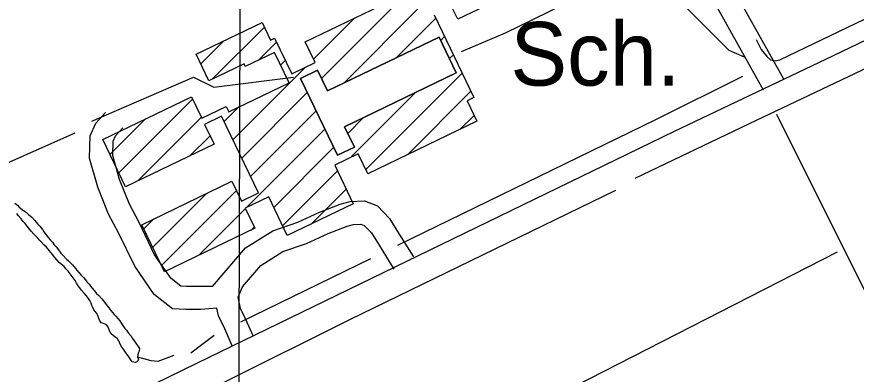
# Model space of a CAD drawing. Extents: x 3161514 to 3199414, y 831166 to 856601.
# Drawn here: x 3175919 to 3177016, y 850531 to 850998 of the extents above; entities that cross this region are included whole.
import ezdxf

# ---------------------------------------------------------------- set-up
doc = ezdxf.new("R2010")
doc.units = 0
for name, color, linetype in [('V-BLDG-IDEN', 7, 'Continuous'), ('V-BLDG-OTLN', 7, 'Continuous'), ('V-GRID-MAJR', 7, 'Continuous'), ('V-ROAD-CNTR', 7, 'Continuous'), ('V-TOPO-SHOR', 7, 'Continuous')]:
    doc.layers.add(name, color=color, linetype=linetype)

msp = doc.modelspace()

# ---------------------------------------------------------------- linework, layer by layer
at = {"layer": 'V-BLDG-OTLN'}
for p, q in [((3176317.2446730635, 850917.3385692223), (3176428.970535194, 851029.0644313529)), ((3176346.4267954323, 850911.1653525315), (3176447.5922815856, 851012.3308386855)), ((3176306.9891416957, 850942.438376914), (3176360.8049249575, 850996.2541601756)), ((3176414.524179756, 850943.9073977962), (3176466.5774924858, 850995.9607105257)), ((3176174.674165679, 850916.1894180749), (3176242.696642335, 850984.2118947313)), ((3176159.5428679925, 850936.4134594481), (3176189.186003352, 850966.0565948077)), ((3176234.9039112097, 850941.0638245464), (3176258.424099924, 850964.5840132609)), ((3176472.9441205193, 850966.9719995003), (3176478.0654100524, 850972.0932890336)), ((3176484.423525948, 850943.0960658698), (3176489.5533276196, 850948.2258675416)), ((3176201.6958582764, 850837.1450934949), (3176296.355241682, 850931.8044769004)), ((3176263.929435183, 850934.7340094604), (3176269.911375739, 850940.715950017)), ((3176375.074054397, 850798.3912552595), (3176501.0412451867, 850924.3584460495)), ((3176213.184005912, 850813.277902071), (3176298.7234474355, 850898.8173435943)), ((3176355.774596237, 850814.4471361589), (3176440.2137494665, 850898.8862893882)), ((3176430.004822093, 850817.966683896), (3176512.5291627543, 850900.4910245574)), ((3176052.5059617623, 850794.0212141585), (3176148.8372529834, 850890.3525053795)), ((3176190.207710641, 850861.0122849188), (3176209.2667676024, 850880.0713418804)), ((3176077.428119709, 850783.5880330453), (3176160.324541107, 850866.4844544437)), ((3176224.6721535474, 850789.4107106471), (3176310.2035608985, 850874.9421179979)), ((3176351.573582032, 850845.6014610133), (3176372.1154543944, 850866.1433333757)), ((3176498.1708077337, 850850.7773304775), (3176516.4984713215, 850869.1049940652)), ((3176041.017991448, 850817.8885829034), (3176087.5860779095, 850864.4566693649)), ((3176219.4736047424, 850748.8568227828), (3176321.683674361, 850851.0668924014)), ((3176145.5945323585, 850816.3991066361), (3176171.7412406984, 850842.5458149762)), ((3176254.955607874, 850748.983486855), (3176333.1637878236, 850827.1916668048)), ((3176266.443437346, 850725.1159772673), (3176338.1216935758, 850796.7942334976)), ((3176096.860817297, 850696.9547134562), (3176166.716482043, 850766.8103782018)), ((3176108.34881465, 850673.0873717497), (3176206.1678467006, 850770.9064038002)), ((3176303.924025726, 850727.2412265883), (3176349.6099119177, 850772.9271127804)), ((3176157.2476974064, 850686.6309154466), (3176217.8259444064, 850747.2091624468)), ((3176085.3728199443, 850720.822055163), (3176098.5539051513, 850734.0031403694)), ((3176225.413369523, 850719.441248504), (3176229.3135148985, 850723.3413938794))]:
    msp.add_line(p, q, dxfattribs=at)
for points in [[(3176464.512, 851000.252), (3176516.412, 850892.424), (3176507.37, 850888.072), (3176520.213, 850861.387), (3176377.757, 850792.818), (3176365.168, 850818.969), (3176334.544, 850804.2270000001), (3176358.87, 850753.689), (3176272.663, 850712.194), (3176248.3310000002, 850762.747), (3176217.492, 850747.903), (3176230.1040000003, 850721.699), (3176112.254, 850664.974), (3176082.701, 850726.373), (3176200.349, 850782.998), (3176212.784, 850757.158), (3176235.04, 850767.871), (3176186.877, 850867.932), (3176164.668, 850857.2440000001), (3176177.04, 850831.535), (3176061.271, 850775.811), (3176031.579, 850837.4990000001), (3176147.436, 850893.264), (3176160.91, 850865.268), (3176192.986, 850880.708), (3176196.298, 850873.829), (3176275.008, 850911.715), (3176255.997, 850951.216), (3176217.728, 850932.797), (3176216.1180000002, 850936.139), (3176170.292, 850914.0800000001), (3176153.535, 850948.8960000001), (3176239.7260000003, 850990.384), (3176250.807, 850967.361), (3176255.907, 850969.814), (3176278.367, 850923.147), (3176309.145, 850937.96), (3176296.08, 850965.1), (3176437.5500000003, 851033.194)], [(3176539.182, 851015.544), (3176495.394, 850994.468), (3176488.594, 851008.5970000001)]]:
    msp.add_lwpolyline(points, dxfattribs=at)
for points in [[(3176338.06, 850817.009), (3176289.856, 850917.259), (3176312.133, 850927.97), (3176325.1350000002, 850900.9280000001), (3176470.982, 850971.0530000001), (3176493.387, 850924.453), (3176347.409, 850854.264), (3176360.201, 850827.6560000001)], [(3176338.06, 850817.009), (3176360.201, 850827.6560000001), (3176347.409, 850854.264), (3176493.387, 850924.453), (3176470.982, 850971.0530000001), (3176325.1350000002, 850900.9280000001), (3176312.133, 850927.97), (3176289.856, 850917.259)]]:
    msp.add_lwpolyline(points, close=True, dxfattribs=at)
at = {"layer": 'V-GRID-MAJR'}
msp.add_spline([(3176169.236, 836603.9550000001), (3176186.862, 842663.26), (3176204.497, 848725.65), (3176222.132, 854788.081), (3176222.1410000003, 854791.1240000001)], degree=3, dxfattribs=at)
at = {"layer": 'V-ROAD-CNTR'}
for points in [[(3176711.6135399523, 851680.4266116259), (3176664.981633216, 851658.0176564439), (3176589.9597832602, 851622.1197282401), (3176566.307830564, 851610.003752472), (3176551.507860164, 851598.3927756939), (3176545.8218715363, 851588.182796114), (3176546.1768708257, 851581.6098092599), (3176560.465842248, 851555.296861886), (3176627.74470769, 851432.3641077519), (3176764.487434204, 851192.7755869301), (3176852.058259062, 851039.7748929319), (3176920.40412237, 850916.834138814)], [(3178004.93195331, 851437.1060982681), (3177919.316124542, 851396.4961794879), (3177527.2989085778, 851206.8905586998), (3176975.3950123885, 850941.805088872), (3176777.6954077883, 850848.155276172), (3176154.166654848, 850545.087882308), (3175803.4443562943, 850374.211224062), (3175245.436472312, 850104.33776381), (3174206.5125501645, 849596.8837787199)], [(3176696.676569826, 851251.0664703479), (3176738.4414862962, 851177.8896167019), (3176825.9283113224, 851025.0349224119), (3176894.18417481, 850902.2581679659)], [(3176180.7856016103, 850617.4027376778), (3176159.726643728, 850615.662741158), (3176140.073683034, 850615.6887411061), (3176122.6807178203, 850616.714739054), (3176098.86076546, 850635.2827019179), (3176073.42081634, 850672.125628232), (3176052.39585839, 850715.8005408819), (3176039.281884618, 850740.3154918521), (3176025.072913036, 850775.56142136), (3176014.5629340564, 850813.16634615), (3176015.281932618, 850842.37128774), (3176022.784917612, 850858.7822549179), (3176035.31089256, 850872.8642267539)], [(3176174.8346135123, 850645.6446811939), (3176140.9776812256, 850645.68668111), (3176133.7646956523, 850646.112680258), (3176120.9327213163, 850656.114660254), (3176099.4367643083, 850687.245597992), (3176079.1498048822, 850729.388513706), (3176066.499830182, 850753.0354664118), (3176053.518856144, 850785.2374020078), (3176044.664873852, 850816.91633865), (3176045.1218729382, 850835.487301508), (3176048.1948667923, 850842.2102880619), (3176057.726847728, 850852.92626663)], [(3176174.8346135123, 850645.6446811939), (3176218.1185269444, 850695.9955804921), (3176253.624455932, 850718.6005352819), (3176286.379390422, 850729.74651299), (3176314.532334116, 850742.7504869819), (3176341.838279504, 850753.219466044), (3176354.573254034, 850756.5224594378), (3176373.6682158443, 850757.5524573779), (3176390.26518265, 850750.88647071), (3176406.233150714, 850734.370503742), (3176417.903127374, 850715.435541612), (3176437.2700886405, 850684.4626035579)], [(3176228.3335065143, 850580.490811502), (3176218.287526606, 850603.372765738), (3176211.3665404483, 850617.05173838), (3176208.604545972, 850631.8837087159), (3176214.04553509, 850645.2386820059), (3176237.974487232, 850673.0736263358), (3176266.698429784, 850691.360589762), (3176297.5313681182, 850701.8525687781), (3176326.204310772, 850715.09654229), (3176351.0022611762, 850724.6035232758), (3176359.193244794, 850726.7285190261), (3176368.65022588, 850727.2385180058), (3176373.1452168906, 850725.4325216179), (3176382.403198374, 850715.858540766), (3176392.41517835, 850699.6135732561), (3176411.834139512, 850668.55663537)], [(3176200.8635614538, 850568.4308356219), (3176191.147580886, 850590.5607913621), (3176182.658597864, 850607.339757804), (3176180.7856016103, 850617.40173768)]]:
    msp.add_lwpolyline(points, dxfattribs=at)
at = {"layer": 'V-TOPO-SHOR'}
for p, q in [((3175995.152773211, 850845.9242485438), (3175875.640138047, 850792.8075218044)), ((3176245.2440282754, 850310.3305872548), (3176991.091399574, 850691.0004622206)), ((3176212.1410000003, 850599.4400000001), (3176381.779, 850682.459)), ((3176146.488, 850559.01), (3176177.313, 850582.0750000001))]:
    msp.add_line(p, q, dxfattribs=at)
for points in [[(3176683.4570238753, 851228.807320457), (3176756.4925231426, 851100.4418975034), (3176760.918917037, 851087.1627158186), (3176756.4925231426, 851078.3099280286), (3176670.177842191, 851031.8327921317), (3176557.3047978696, 850976.5028684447), (3176499.7616772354, 850952.1577020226)], [(3176437.7921627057, 851118.1474730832), (3176625.913903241, 851200.0357601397), (3176774.198098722, 851029.6195951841), (3176849.4467949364, 850954.3708989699), (3176869.3655674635, 850945.51811118)], [(3177384.68, 851099.875), (3176875.898, 850857.834), (3176726.269, 850786.701)], [(3176885.085, 850968.098), (3176891.661, 850954.905), (3176899.091, 850945.6460000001), (3176903.8200000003, 850941.701), (3176909.534, 850940.245), (3176915.7090000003, 850941.6560000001), (3177026.502, 850994.8), (3177073.898, 851016.601)], [(3176416.955, 850699.812), (3176753.812, 850863.775), (3176867.415, 850920.066)], [(3176017.2847426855, 850861.4166271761), (3176150.0765595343, 850918.9597478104), (3176176.6349229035, 850905.6805661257), (3176280.655179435, 850918.9597478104)], [(3176911.4163094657, 850870.8227142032), (3177130.522807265, 850432.609718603), (3177289.872987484, 850122.7621459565), (3177400.5328348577, 849901.4424512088), (3177582.0149845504, 849538.4781518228), (3177714.806801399, 849270.6813211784)], [(3176701.201, 850771.126), (3176354.092, 850602.436), (3176190.752, 850520.8910000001), (3176150.429, 850497.873), (3176113.1, 850468.128)], [(3175916.737, 850754.5260000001), (3175920.2830000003, 850751.731), (3175922.7090000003, 850749.415), (3175926.25, 850746.394), (3175929.355, 850744.059), (3175932.02, 850742.187), (3175935.339, 850739.398), (3175938.872, 850736.15), (3175942.835, 850731.988), (3175946.569, 850727.608), (3175949.432, 850724.603), (3175952.934, 850720.001), (3175954.898, 850717.245), (3175957.732, 850713.11), (3175960.804, 850709.421), (3175963.436, 850706.198), (3175965.853, 850703.429), (3175968.253, 850699.982), (3175970.901, 850697.434), (3175973.748, 850693.752), (3175976.803, 850689.388), (3175979.886, 850686.152), (3175984.514, 850681.523), (3175986.724, 850679.437), (3175988.9250000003, 850677.1240000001), (3175992.008, 850673.889), (3175995.96, 850669.2760000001), (3175997.937, 850666.97), (3176001.019, 850663.735), (3176003.21, 850660.9720000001), (3176006.507, 850657.277), (3176008.924, 850654.508), (3176010.894, 850651.9770000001), (3176013.9790000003, 850648.741), (3176015.717, 850645.9890000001), (3176017.694, 850643.683), (3176020.557, 850640.676), (3176023.623, 850636.764), (3176026.045, 850634.221), (3176030.68, 850629.818), (3176033.7290000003, 850625.228), (3176035.921, 850622.465), (3176039.654, 850618.083), (3176042.2800000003, 850614.632), (3176046.667, 850609.331), (3176048.8680000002, 850607.019), (3176051.281, 850604.025), (3176053.913, 850600.802), (3176056.313, 850597.355), (3176058.058, 850594.8300000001), (3176060.677, 850591.1510000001), (3176062.649, 850588.62), (3176065.49, 850584.712), (3176068.556, 850580.799), (3176070.522, 850578.04), (3176072.701, 850574.827), (3176074.886, 850571.839), (3176077.9420000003, 850567.474), (3176079.687, 850564.947), (3176079.154, 850561.572), (3176077.954, 850558.666), (3176077.161, 850553.943), (3176078.218, 850550.982), (3176077.018, 850548.076), (3176074.272, 850546.562), (3176070.227, 850547.339), (3176067.39, 850551.471), (3176064.9960000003, 850555.1410000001), (3176062.377, 850558.8200000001), (3176060.632, 850561.3470000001), (3176058.8850000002, 850563.872), (3176056.468, 850566.6410000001), (3176054.5270000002, 850570.301), (3176052.829, 850574.857), (3176050.431, 850578.304), (3176047.754, 850579.724), (3176045.321, 850581.8150000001), (3176042.4420000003, 850584.143), (3176040.703, 850586.8960000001), (3176039.656, 850590.308), (3176038.378, 850593.5), (3176036.4020000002, 850595.806), (3176032.599, 850597.2540000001), (3176029.461, 850598.233), (3176027.293, 850601.899), (3176026.2460000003, 850605.311), (3176024.325, 850609.8740000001), (3176022.359, 850612.633), (3176020.168, 850615.3960000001), (3176018.654, 850618.142), (3176017.366, 850620.882), (3176016.541, 850624.0650000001), (3176014.591, 850627.4990000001), (3176012.846, 850630.027)], [(3176012.846, 850630.027), (3176010.005, 850633.932), (3176007.595, 850636.9280000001), (3176003.8510000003, 850640.858), (3176001.67, 850644.072), (3175999.704, 850646.828), (3175997.531, 850650.2710000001), (3175995.803, 850653.4720000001), (3175992.95, 850656.929), (3175989.02, 850662.444), (3175986.828, 850665.207), (3175983.5270000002, 850668.674), (3175981.114, 850671.6680000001), (3175977.3540000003, 850674.9230000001), (3175974.927, 850677.2390000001), (3175971.843, 850680.4770000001), (3175969.207, 850683.475), (3175966.145, 850687.6140000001), (3175961.974, 850692.458), (3175958.021, 850697.0700000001), (3175954.9390000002, 850700.306), (3175951.414, 850704.0040000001), (3175948.981, 850706.0970000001), (3175947.011, 850708.6290000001), (3175944.809, 850710.941), (3175941.725, 850714.177), (3175938.203, 850717.875), (3175933.171, 850724.546), (3175930.3140000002, 850727.778), (3175927.897, 850730.544), (3175925.0500000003, 850734.229), (3175921.319, 850738.609), (3175919.343, 850740.915)], [(3176077.161, 850553.943), (3176094.541, 850549.149), (3176104.238, 850548.184), (3176124.808, 850555.942)]]:
    msp.add_lwpolyline(points, dxfattribs=at)

# ---------------------------------------------------------------- texts
at = {"layer": 'V-BLDG-IDEN'}
msp.add_text('Sch.', height=82.99983200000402, dxfattribs=at).set_placement((3176564.036835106, 850907.9181566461))

doc.saveas('drawing.dxf')
